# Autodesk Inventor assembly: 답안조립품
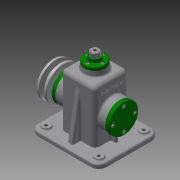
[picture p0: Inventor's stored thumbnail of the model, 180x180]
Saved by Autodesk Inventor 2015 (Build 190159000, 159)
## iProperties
Created: 2016-06
Part Number: 답안조립품
Document SubType Name: Assembly
Designer: Administrator
Author: Administrator
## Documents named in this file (19)
- G:\Manufacturing2급-구철민\답안조립품.iam
- G:\Manufacturing2급-구철민\본체.ipt
- G:\Manufacturing2급-구철민\베어링 15 x 35 x 11.ipt
- G:\Manufacturing2급-구철민\편심축.ipt
- G:\Manufacturing2급-구철민\멈춤링 15 x 1.ipt
- G:\Manufacturing2급-구철민\링크.ipt
- G:\Manufacturing2급-구철민\상부부시.ipt
- G:\Manufacturing2급-구철민\볼트 M3 x 8.ipt
- G:\Manufacturing2급-구철민\슬라이드바.ipt
- G:\Manufacturing2급-구철민\고정핀.ipt
- G:\Manufacturing2급-구철민\멈춤링 6 x 5.ipt
- G:\Manufacturing2급-구철민\뒤커버.ipt
- G:\Manufacturing2급-구철민\볼트 M4 x 10.ipt
- G:\Manufacturing2급-구철민\앞커버.ipt
- G:\Manufacturing2급-구철민\오일실 15 25 7.ipt
- G:\Manufacturing2급-구철민\키 5 x 5 x 14.ipt
- G:\Manufacturing2급-구철민\V-벨트풀리.ipt
- G:\Manufacturing2급-구철민\와셔.ipt
- G:\Manufacturing2급-구철민\볼트 M6 x 12.ipt
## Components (15 placed, 5 different names)
1. 고정핀:1
2. V-벨트풀리:1
3. ISO 4018 M6 x 12:1 — 각도:1
4. ISO 4762 M3 x 8:1
5. ISO 4762 M3 x 8:2
6. ISO 4762 M3 x 8:3
7. ISO 4762 M3 x 8:4
8. ISO 4762 M4 x 10:1
9. ISO 4762 M4 x 10:2
10. ISO 4762 M4 x 10:3
11. ISO 4762 M4 x 10:4
12. ISO 4762 M4 x 10:5
13. ISO 4762 M4 x 10:6
14. ISO 4762 M4 x 10:7
15. ISO 4762 M4 x 10:8
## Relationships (1: Angle 1)
- 각도:1 [Angle]: ISO 4018 M6 x 12:1
